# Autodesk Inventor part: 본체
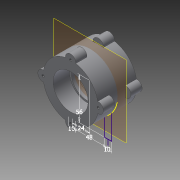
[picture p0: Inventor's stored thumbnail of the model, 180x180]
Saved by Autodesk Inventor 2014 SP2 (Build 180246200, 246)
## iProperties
Created: 2015-03
Part Number: 본체
Material: 일반
Document SubType Name: Modeling
Designer: 2015.02.10
Density: 1 g/cm^3
Appearance: 기본값
Author: 2015.02.10
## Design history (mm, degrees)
sketch "스케치1"
  geometry: C1 r 37 at (0, 0); 1 further point
  constraints: 1 centre point, 1 coincident
  dimensions: "d0" = 74 diameter of C1
extrude "돌출1" new body sketch "스케치1" distance "d1" = 52; taper "d2" = 0 deg
sketch "스케치2"
  geometry: A1 r 7 centre (-0.033, 37) between (6.936, 36.344) and (-7.001, 36.332); A2 r 37 centre (0, 0) between (-0.033, 37) and (-7.001, 36.332) reference; 2 further points
  constraints: 5 point on circle, 1 centre point, 2 other
  dimensions: "d3" = 14 diameter of A1; "d4" = 36.99999 distance of point (0, 0) A1.centre
extrude "돌출2" join sketch "스케치2" distance "d5" = 15; taper "d6" = 0 deg
node "작업 평면1"
sketch "스케치3"
  geometry: C1 r 23.5 at (0, 0); 1 further point
  constraints: 1 centre point, 1 coincident
  dimensions: "d10" = 47 diameter of C1
extrude "돌출3" cut sketch "스케치3" distance "d11" = 22; taper "d12" = 0 deg
sketch "스케치4"
  geometry: C1 r 21 at (0, 0); 1 further point
  constraints: 1 centre point, 1 coincident
  dimensions: "d13" = 42 diameter of C1
extrude "돌출4" cut sketch "스케치4" stored distance "d14" = 22; taper "d15" = 0 deg
sketch "스케치6" dims "d16" = 74
  geometry: C1 r 2 at (0, 37); A1 r 7 centre (-0.033, 37) between (6.936, 36.344) and (-7.001, 36.332) reference; 2 further points
  constraints: 1 centre point, 1 coincident, 1 vertical alignment, 2 other
  dimensions: "d17" = 4 diameter of C1; "d18" = 0.00001 vertical distance of C1.centre A1.centre
hole "구멍1" sketch "스케치6" at (0, 37) diameter "d19" = 3.242; stored, may be unused: countersink angle "d23" = 90 deg, drill point angle "d25" = 118 deg; dims "d20" = 8, "d21" = 4, "d22" = 2, "d24" = 11
sketch "스케치8"
  geometry: 1 further point
sketch "스케치9"
  geometry: L1 (29, -22.978)-(29, -56); L2 (29, -56)-(19, -56); L3 (19, -56)-(19, -31.749); L4 (-29, -22.978)-(-29, -56); L5 (-29, -56)-(-19, -56); L6 (-19, -56)-(-19, -31.749); L7 (-24, -56)-(-24, -60.968); L8 (24, -56)-(24, -63.456); A1 r 37 centre (0, 0) between (7.001, -36.332) and (36.344, -6.936) reference; A2 r 37 centre (0, 0) between (-36.332, -7.001) and (-6.936, -36.344) reference; 1 further point
  constraints: 16 end point, 5 parallel, 4 point on circle, 2 midpoint, 2 perpendicular, 1 vertical
  dimensions: "d29" = 56 distance from line of L2 point (0, 0); "d30" = 10 distance of L4.end L5.end; "d31" = 10 distance of L1.end L2.end; "d32" = 48 distance between parallel lines of L7 L8; "d33" = 24 horizontal distance of L7.start point (0, 0)
node "솔리드1"
pattern_circular "원형 패턴1" dims angle "d8" = 360 deg
mirror "대칭1"
mirror "대칭2"
pattern_circular "원형 패턴2" dims angle "d27" = 360 deg
mirror "대칭3"
node "투영된 루프1"
